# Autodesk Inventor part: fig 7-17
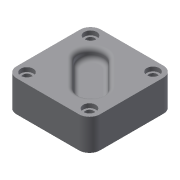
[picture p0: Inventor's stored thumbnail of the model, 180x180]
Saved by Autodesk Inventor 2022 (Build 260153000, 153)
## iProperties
Created: 2001-12
Part Number: fig 7-17
Document SubType Name: Modeling
Designer: Renu Muthoo
Density: 1 g/cm^3
Material: Generic
Appearance: Default
Control State: 0
Master: False
Checked Out: False
Shininess: 77.0
Angle Display Precision: 2
Document Length Units: 11269
Document Angle Units: 11279
Document Time Units: 11290
Document Mass Units: 11283
Document Length Units Precision: 3
Document Angle Units Precision: 2
Density: 0.0
Volumn: 0.0
Area: 0.0
PropertySet Name: Model Information
Author: Renu Muthoo
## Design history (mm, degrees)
sketch "Sketch1"
  geometry: L1 (-20, 20)-(20, 20); L2 (20, 20)-(20, -20.5); L3 (20, -20.5)-(-20, -20.5); L4 (-20, -20.5)-(-20, 20); 1 further point
  constraints: 8 end point, 2 parallel, 1 horizontal, 1 perpendicular, 1 other
  dimensions: "d0" = 40 distance of L1.start L1.end; "d1" = 40.5 distance of L3.end L1.start; "d100" = 20 distance from line of L4 point (0, 0); "d101" = 20 distance from line of L1 point (0, 0)
extrude "Extrusion1" new body sketch "Sketch1" distance "d2" = 15; taper "d3" = 0 deg
workplane "Work Plane1"
workplane "Work Plane2"
workplane "Work Plane3"
fillet "Fillet1" dims "d32" = 5
hole "Hole3" diameter "d66" = 4; stored, may be unused: countersink angle "d70" = 90 deg, drill point angle "d72" = 118 deg; dims "d64" = 10, "d65" = 10, "d67" = 6, "d68" = 6, "d69" = 2, "d71" = 8
hole "Hole4" diameter "d75" = 4; stored, may be unused: countersink angle "d79" = 90 deg, drill point angle "d81" = 118 deg; dims "d73" = 10, "d74" = 10, "d76" = 6, "d77" = 6, "d78" = 2, "d80" = 8
hole "Hole5" diameter "d84" = 4; stored, may be unused: countersink angle "d88" = 90 deg, drill point angle "d90" = 118 deg; dims "d82" = 10, "d83" = 10, "d85" = 6, "d86" = 6, "d87" = 2, "d89" = 8
hole "Hole6" diameter "d93" = 4; stored, may be unused: countersink angle "d97" = 90 deg, drill point angle "d99" = 118 deg; dims "d91" = 10, "d92" = 10, "d94" = 6, "d95" = 6, "d96" = 2, "d98" = 8
fillet "Fillet2" dims "d61" = 2
body "Solid1"
sketch "Sketch8"
  geometry: L1 (-9.844, 1.64)-(1.983, -10.187); L2 (10.469, -1.701)-(-1.358, 10.126); A1 r 6 centre (-5.601, 5.883) between (-1.358, 10.126) and (-9.844, 1.64); A2 r 6 centre (6.226, -5.944) between (1.983, -10.187) and (10.469, -1.701)
  constraints: 4 end point, 4 point on circle, 4 tangent, 2 centre point, 1 parallel
  dimensions: "d29" = 6 radius of A2
extrude "Extrusion2" cut sketch "Sketch8" distance "d30" = 5; taper "d31" = 0 deg
